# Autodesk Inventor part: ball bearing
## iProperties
Created: 2010-10
Part Number: ball bearing
Document SubType Name: Modeling
Designer: Administrator
Density: 7.85 g/cm^3
Material: Steel
Mass: 91.3258 g
Surface Area: 41.5127 cm^2
Volume: 11.6339 cm^3
Author: Administrator
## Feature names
1. Base1
